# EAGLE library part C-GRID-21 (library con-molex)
CONNECTOR wire to board 2.54 mm (0.100") pitch header
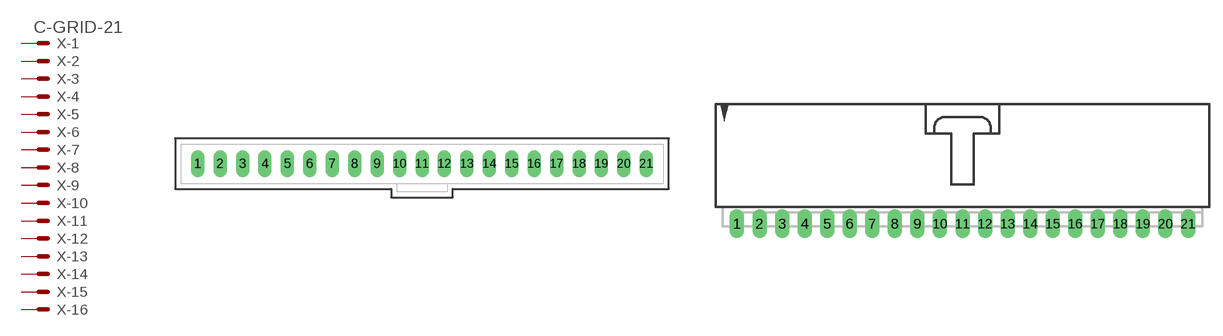
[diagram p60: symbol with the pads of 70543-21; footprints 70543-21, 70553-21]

Designator prefix X; gates -1=MV -2=M -3=M -4=M -5=M -6=M -7=M -8=M -9=M -10=M -11=M -12=M -13=M -14=M -15=M -16=M -17=M -18=M -19=M -20=M -21=M

## C-GRID-21-70543 (OC_FARNELL: unknown; OC_NEWARK: unknown)  [70543-21]
1  -1:S  pas
2  -2:S  pas
3  -3:S  pas
4  -4:S  pas
5  -5:S  pas
6  -6:S  pas
7  -7:S  pas
8  -8:S  pas
9  -9:S  pas
10  -10:S  pas
11  -11:S  pas
12  -12:S  pas
13  -13:S  pas
14  -14:S  pas
15  -15:S  pas
16  -16:S  pas
17  -17:S  pas
18  -18:S  pas
19  -19:S  pas
20  -20:S  pas
21  -21:S  pas

## C-GRID-21-70553 (OC_FARNELL: unknown; OC_NEWARK: unknown)  [70553-21]
Pads as for 70543-21

## Footprint 70543-21 (pad centres in mm)
C-Grid SL Connector vertical, 21 pin
drill 1.016 long: 1 -25.4,0; 2 -22.86,0; 3 -20.32,0; 4 -17.78,0; 5 -15.24,0; 6 -12.7,0; 7 -10.16,0; 8 -7.62,0; 9 -5.08,0; 10 -2.54,0; 11 0,0; 12 2.54,0; 13 5.08,0; 14 7.62,0; 15 10.16,0; 16 12.7,0; 17 15.24,0; 18 17.78,0; 19 20.32,0; 20 22.86,0; 21 25.4,0

## Footprint 70553-21 (pad centres in mm)
C-Grid SL Connector right angle, 21 pin
drill 1.092 long: 1 -25.4,-7.62; 2 -22.86,-7.62; 3 -20.32,-7.62; 4 -17.78,-7.62; 5 -15.24,-7.62; 6 -12.7,-7.62; 7 -10.16,-7.62; 8 -7.62,-7.62; 9 -5.08,-7.62; 10 -2.54,-7.62; 11 0,-7.62; 12 2.54,-7.62; 13 5.08,-7.62; 14 7.62,-7.62; 15 10.16,-7.62; 16 12.7,-7.62; 17 15.24,-7.62; 18 17.78,-7.62; 19 20.32,-7.62; 20 22.86,-7.62; 21 25.4,-7.62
